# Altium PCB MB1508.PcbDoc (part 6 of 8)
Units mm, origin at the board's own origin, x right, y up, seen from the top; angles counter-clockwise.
Board outline 129 x 77 mm, 4 copper layers (Top Layer, GND, POWER, Bottom Layer), stack 1.582 mm thick; 399 components, 297 nets, 1407 pads, 1316 vias.
Unrouted connection lines stored in the file: 535.
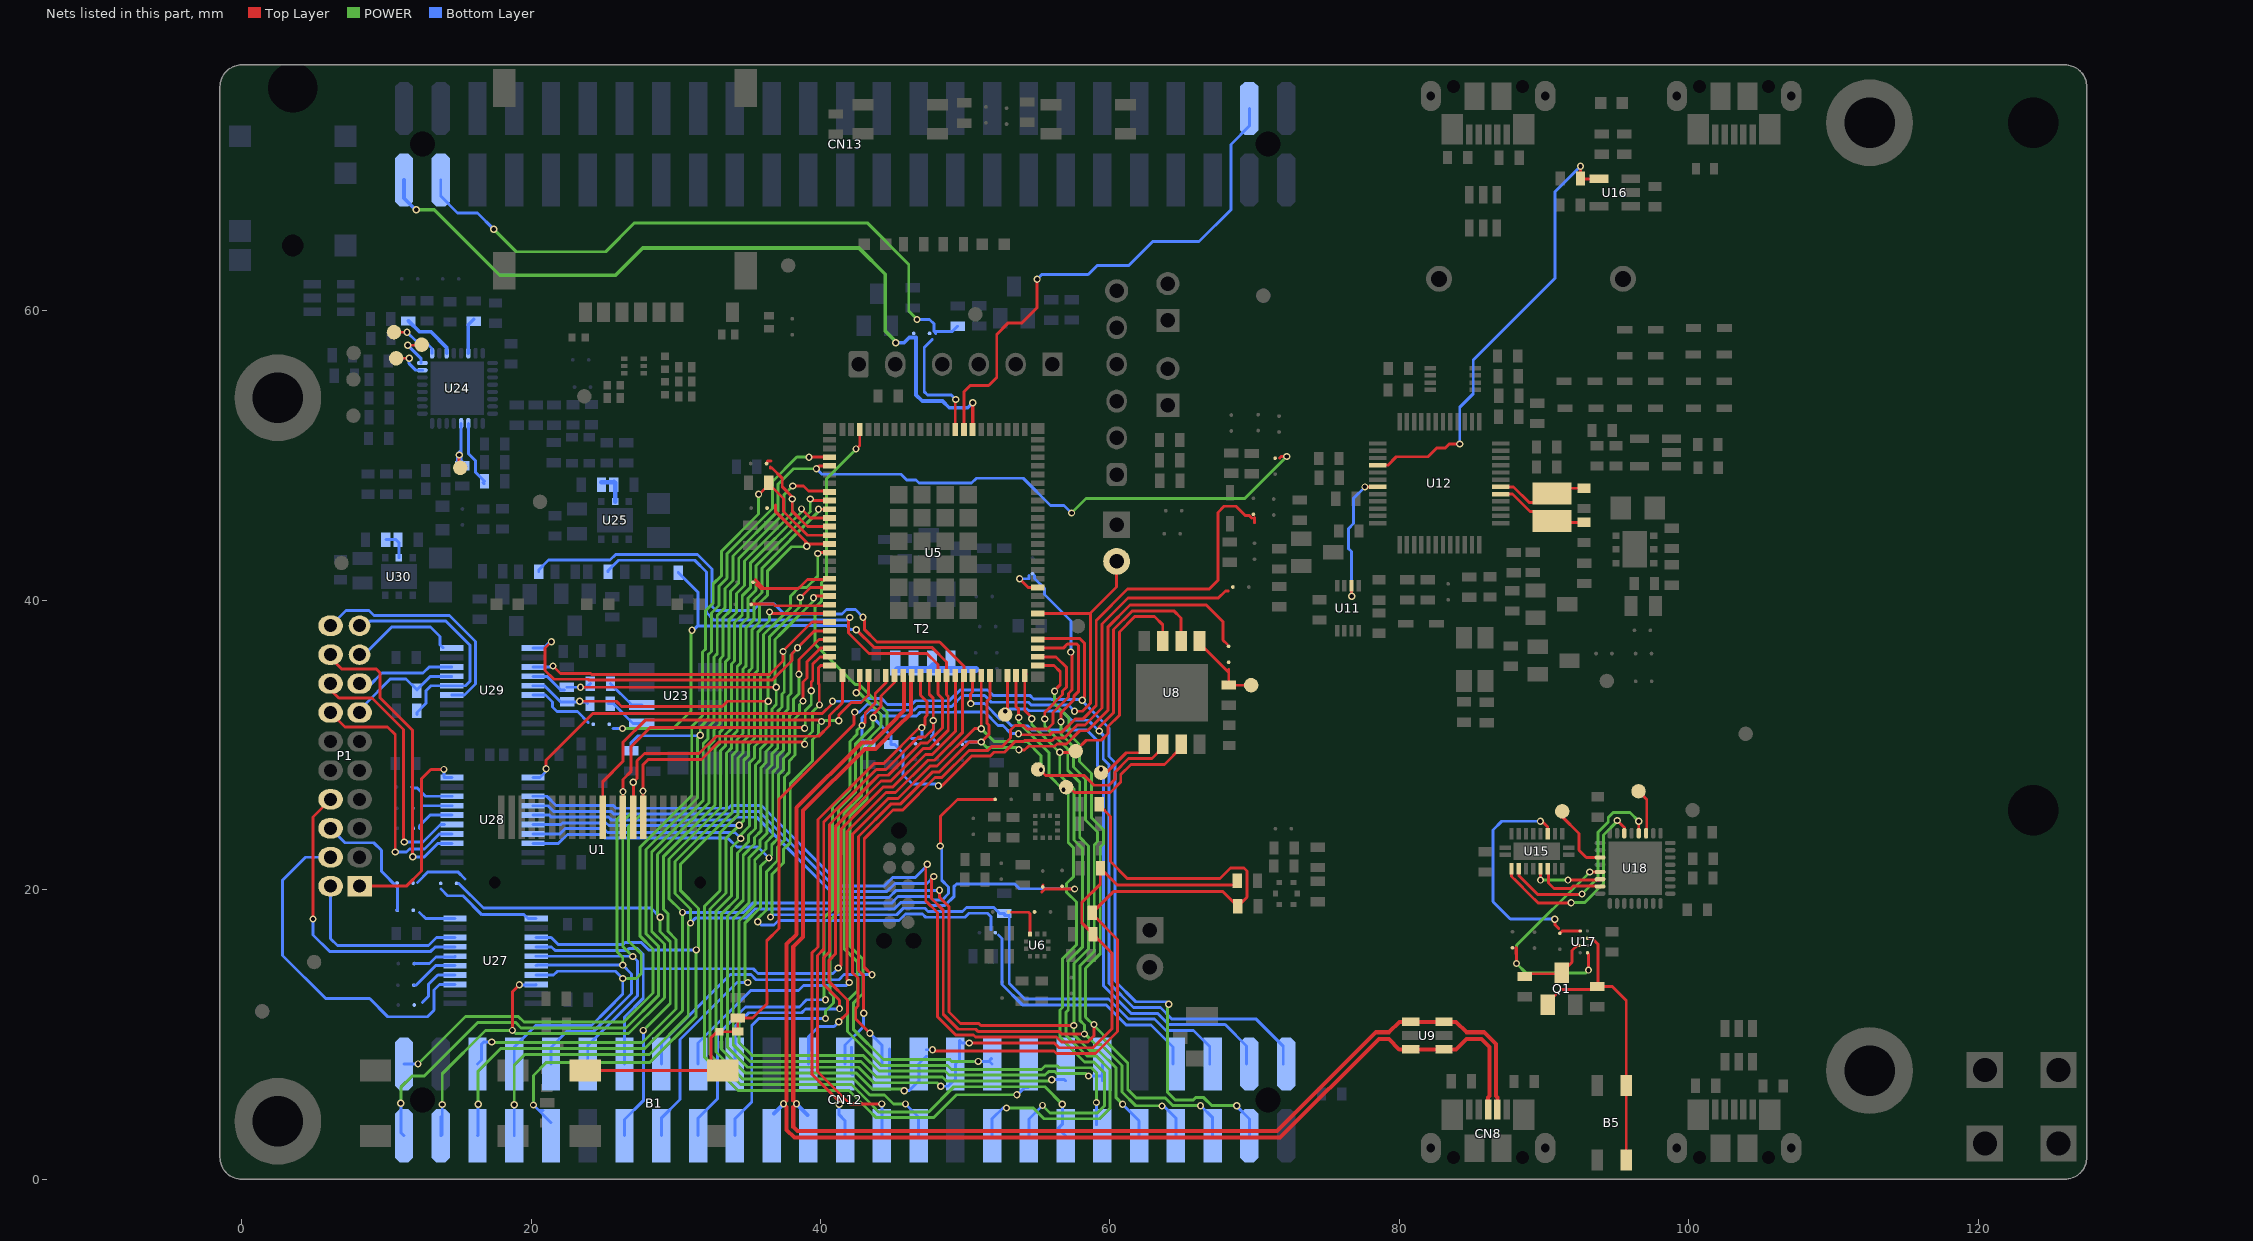
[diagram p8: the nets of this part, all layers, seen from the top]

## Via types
v1: diameter 0.5, hole 0.3, Top Layer to Bottom Layer, tented both sides, 1301 vias
v2: diameter 0.65, hole 0.4, Top Layer to Bottom Layer, tented both sides, 14 vias
v3: diameter 0.5/0.5/0.5/0.5 (per signal layer), hole 0.3, Top Layer to Bottom Layer, tented both sides, 1 vias

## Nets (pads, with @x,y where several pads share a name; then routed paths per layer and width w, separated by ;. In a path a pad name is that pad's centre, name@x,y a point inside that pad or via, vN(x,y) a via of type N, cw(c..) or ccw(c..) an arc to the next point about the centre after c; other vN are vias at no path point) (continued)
NetR93_2: R93.2 U24.3 | length 4.6
  Bottom Layer w0.2: U24.3@15.663,52.225 15.663,50.141 16.16,49.644 16.16,48.851 R93.2@16.78,48.231 ; R93.2@16.678,48.13 R93.2@16.755,48.054
NetR95_2: R95.2 R104.1 U25.5 | length 2.3
  Bottom Layer w0.3: R104.1@24.843,48.155 25.679,48.155 25.731,48.208 25.809,48.129 U25.5@25.809,46.823
NetR97_2: R97.2 TP10.1 U24.4 | length 5.8
  Top Layer w0.2: v1(15.031,50.047) 15.031,49.232 TP10.1@15.106,49.158
  Bottom Layer w0.2: R97.2@14.913,49.471 14.913,50.127 15.163,50.377 ; v1@15.057,50.047 R97.2@15.057,49.455 ; R97.2@15.163,49.612 15.163,50.377 ; U24.4@15.163,52.225 15.163,50.377 ; R97.2@15.213,49.099 15.213,49.299 R97.2@15.057,49.455 ; R97.2@15.213,49.612 R97.2@15.057,49.455
NetR99_1: R99.1 U23.6 | length 2.8
  Bottom Layer w0.2: R99.1@25.493,34.239 26.966,32.766 U23.6@27.654,32.766
NetR100_1: R100.1 U23.5 | length 2.9
  Bottom Layer w0.2: R100.1@25.306,32.867 25.68,32.867 27.051,31.496 U23.5@27.654,31.496
NetR102_1: R102.1 U24.22 | length 2.5
  Bottom Layer w0.254: U24.22@15.663,57.075 15.663,59.05 R102.1@16.032,59.419
NetR110_1: R110.1 U24.19 | length 3.8
  Bottom Layer w0.254: R110.1@11.527,59.31 12.285,58.552 13.086,58.552 14.163,57.475 U24.19@14.163,57.075
NetR117_2: R117.2 R119.1 U30.5 | length 2
  Bottom Layer w0.2: R119.1@9.965,44.199 10.65,44.199 10.866,43.983 U30.5@10.866,42.943
NetSB1_2: SB1.2 U5.68 | length 6.3
  Top Layer w0.2: 35.496,41.43 36.099,40.826 ; 35.566,41.114 35.854,40.827 38.487,40.827 39.107,41.447 40.567,41.447 U5.68@40.613,41.494
NetSB4_1: SB4.1 U5.71 | length 5.5
  Top Layer w0.2: SB4.1@35.207,39.716 35.23,39.739 36.742,39.739 36.854,39.626 40.546,39.626 U5.71@40.613,39.694
NetSB9_1: SB9.1 SB13.1 U6.5 | length 2.7
  Top Layer w0.2: 53.198,18.444 54.374,18.444 54.48,18.338 U6.5@54.48,16.939
NetSB30_1: SB30.1 U17.D2 U18.5 | length 17.2
  Top Layer w0.2: 88.072,15.565 88.072,16 88.097,15.975 v1(88.097,14.905) ; U17.D2@92.999,15.65 93.075,15.573 v1(93.075,14.448) ; v1(93.165,21.229) U18.5@93.872,21.229
  POWER w0.2: v1(93.075,14.448) 92.862,14.234 88.768,14.234 v1(88.097,14.905) 88.097,16.16 v1(93.165,21.229)
NetSB32_1: SB32.1 U15.14 U17.A1 | length 16.6
  Top Layer w0.2: v1(89.746,24.731) 89.858,24.731 90.256,24.332 U15.14@90.256,23.858 ; v1(90.745,17.966) 90.745,17.591 91.018,17.318 ; SB32.1@91.094,16.988 91.256,17.15 U17.A1@92.499,17.15
  Bottom Layer w0.2: v1(89.746,24.731) 87.077,24.731 86.465,24.119 86.465,19.176 87.671,17.97 90.741,17.97 v1(90.745,17.966)
NetSB42_2: SB42.2 T2.5 T2.6 T2.7 T2.8 | length 5.8
  Bottom Layer w0.5: T2.8@45.315,35.216 T2.6@47.553,35.216 ; T2.6@47.825,35.488 T2.6@47.553,35.216 ; SB42.2@50.722,35.216 T2.6@47.553,35.216
NetSB49_2: SB49.2 U29.6 | length 4.8
  Bottom Layer w0.2: U29.6@20.121,33.448 21.002,33.448 21.473,32.977 21.473,32.629 21.794,32.309 23.209,32.309 23.954,31.563
NetSB53_2: SB53.2 U27.1 | length 7.4
  Bottom Layer w0.2: 13.769,20.046 14.231,19.584 15.291,19.584 16.597,18.278 19.511,18.278 19.786,18.004 U27.1@20.353,18.004
NetSB57_1: SB57.1 U27.20 | length 2.6
  Bottom Layer w0.2: 12.292,18.431 12.719,18.004 U27.20@14.753,18.004
NetTP3_1: TP3.1 U24.17 | length 3.4
  Top Layer w0.2: TP3.1@10.526,58.527 v1(11.426,58.527)
  Bottom Layer w0.2: v1(11.426,58.527) 12.039,57.914 12.653,57.914 13.163,57.403 U24.17@13.163,57.075
NetTP4_1: TP4.1 U24.16 | length 2.6
  Top Layer w0.2: v1(11.477,57.627) 12.398,57.627 TP4.1@12.436,57.665
  Bottom Layer w0.2: v1(11.477,57.627) 12.405,56.698 U24.16@12.405,56.4
NetTP5_1: TP5.1 U24.15 | length 2.4
  Top Layer w0.2: TP5.1@10.677,56.727 v1(11.577,56.727)
  Bottom Layer w0.2: v1(11.577,56.727) 11.577,56.352 12.029,55.9 U24.15@12.488,55.9
NetTP21_1: TP21.1 U18.3 | length 4.8
  Top Layer w0.2: TP21.1@91.256,25.416 91.256,25.043 92.415,23.884 92.415,22.734 92.92,22.229 U18.3@93.872,22.229
NetTP23_1: TP23.1 U18.27 | length 3.2
  Top Layer w0.2: TP23.1@96.528,26.807 97.097,26.238 97.097,23.954 U18.27@97.047,23.904
NetU11_2: U11.2 U12.31 | length 9.8
  Top Layer w0.2: v1@76.699,40.507 U11.2@76.699,41.001 U11.2@76.699,41.255 ; v1(77.622,47.838) U12.31@78.519,47.838
  Bottom Layer w0.2: v1(76.714,40.273) 76.699,40.289 76.699,43.367 76.475,43.59 76.475,44.933 76.842,45.3 76.842,47.058 v1(77.622,47.838)
NetU15_2: U15.2 U18.30 | length 14
  Top Layer w0.2: U15.2@87.756,21.458 87.756,20.918 88.09,20.584 89.036,19.638 89.578,19.096 v1(91.869,19.096) ; v1(95.057,24.786) 95.547,24.295 U18.30@95.547,23.904
  POWER w0.2: v1(91.869,19.096) 91.895,19.122 92.813,19.122 94.115,20.425 94.115,21.622 ; 94.115,21.623 94.115,23.791 95.057,24.733 v1(95.057,24.786)
NetU15_3: U15.3 U18.28 | length 14.8
  Top Layer w0.2: U15.3@88.256,21.458 88.252,21.455 U15.3@88.254,21.453 ; U15.3@88.306,21.401 U15.3@88.254,21.453 ; v1(92.618,19.706) 92.596,19.684 89.556,19.684 88.482,20.758 88.254,20.986 U15.3@88.254,21.453 ; U18.28@96.547,23.904 v1(96.547,24.739)
  POWER w0.2: v1(92.618,19.706) 93.715,20.803 93.715,21.457 ; 93.715,21.457 93.715,23.957 94.435,24.677 94.435,24.986 94.785,25.336 95.95,25.336 v1(96.547,24.739)
NetU15_6: U15.6 U18.6 | length 4.9
  Top Layer w0.2: v1@89.756,20.704 U15.6@89.756,21.458 ; v1(91.651,20.667) 91.663,20.679 93.822,20.679 U18.6@93.872,20.729
  POWER w0.2: v1(89.756,20.667) v1(91.651,20.667)
NetU15_7: U15.7 U18.7 | length 4.8
  Top Layer w0.2: U15.7@90.256,21.458 90.306,21.408 90.306,20.472 90.694,20.084 91.846,20.084 92.018,20.256 93.599,20.256 93.66,20.195 93.838,20.195 U18.7@93.872,20.229
NRST: B1.1 B1.2 C6.2 JP2.2 R12.2 U4.1 U5.7 | length 71.4
  Top Layer w0.2: B1.1@23.75,7.5 B1.2@33.25,7.5 ; B1.2@32.429,7.868 32.429,9.771 32.848,10.19 C6.2@33.021,10.19 34.249,10.19 U4.1@34.278,10.22 R12.2@34.278,11.129 35.3,11.129 36.295,12.124 36.295,12.923 ; 36.288,12.923 36.288,16.476 37.126,17.313 37.126,26.252 42.314,31.44 42.314,32.222 v1(42.368,32.276) ; U5.7@55.013,39.094 58.629,39.094 58.655,39.119 ; v1(57.55,32.337) 58.104,32.337 58.655,32.888 58.655,39.119 ; JP2.2@60.464,42.689 60.464,40.929 58.655,39.119
  Bottom Layer w0.2: v1(42.368,32.276) 42.692,32.276 43.246,32.829 44.033,32.829 44.459,32.403 46.471,32.403 46.731,32.663 49.069,32.663 49.819,33.414 51.346,33.414 51.801,32.959 54.372,32.959 54.558,32.773 55.773,32.773 55.785,32.76 57.128,32.76 v1(57.55,32.337)
OSC_IN: C36.2 U12.5 X1.1 | length 6.6
  Top Layer w0.2: U12.5@87.019,47.338 87.83,47.338 89.029,46.138 89.588,46.138 90.244,45.482 X1.1@90.555,45.482 90.646,45.391 C36.2@92.763,45.391
OSC_OUT: C37.2 U12.6 X1.2 | length 6.6
  Top Layer w0.2: U12.6@87.019,47.838 87.895,47.838 88.985,46.748 89.921,46.748 90.915,47.742 C37.2@92.768,47.742
PA0: CN12.3 U5.4 U28.1 | length 87.6
  Top Layer w0.2: v1(21.04,28.368) 21.04,28.947 24.262,32.169 38.545,32.169 38.55,32.174 40.127,32.174 v1@40.83,32.877 ; U5.4@55.013,37.294 55.092,37.373 57.901,37.373 58.242,37.032 58.242,33.337 58.011,33.105 58.017,33.098 v1(58.087,33.098)
  POWER w0.2: v1(64.064,12.093) 63.988,12.018 63.988,6.001 64.509,5.48 65.758,5.48 65.908,5.63 66.49,5.63 67.04,5.08 v1(68.762,5.08)
  Bottom Layer w0.2: U28.1@20.131,27.757 20.618,27.757 21.04,28.179 v1(21.04,28.368) ; v1(40.83,33.023) 42.874,33.023 43.08,33.229 44.198,33.229 44.625,32.803 46.305,32.803 46.565,33.063 48.903,33.063 49.654,33.814 51.542,33.814 51.921,33.434 54.462,33.434 54.723,33.173 55.938,33.173 55.951,33.16 58.025,33.16 v1(58.087,33.098) 58.084,33.095 58.084,33.041 59.942,31.183 59.942,29.214 59.937,29.208 59.937,29.206 60.35,28.792 60.35,13.698 61.786,12.262 63.896,12.262 v1(64.064,12.093) ; v1(68.762,5.08) 68.762,5.044 69.64,4.166 CN12.3@69.64,3.005
PA0_C: P1.1 U28.20 | length 14
  Top Layer w0.2: P1.1@8.15,20.246 11.38,20.246 12.431,21.297 12.431,27.676 13.072,28.317 v1(13.977,28.317)
  Bottom Layer w0.2: v1(13.977,28.317) 13.977,27.782 14.002,27.757 U28.20@14.531,27.757
PA1: CN12.5 U5.1 U28.3 | length 96
  Top Layer w0.2: v1(47.376,21.757) 47.276,21.656 47.276,19.228 48.081,18.423 48.081,11.226 49.35,9.957 50.565,9.957 50.706,9.816 56.313,9.816 56.649,9.479 58.465,9.479 58.896,9.911 v1(58.896,10.69) ; U5.1@55.013,35.494 56.14,35.494 56.565,35.069 56.565,34.17 56.106,33.71 v1(56.179,33.71)
  POWER w0.2: v1(56.179,33.71) 56.179,32.856 57.156,31.879 57.156,31.834 57.161,31.829 57.161,30.776 57.893,30.044 57.893,28.852 58.719,28.025 58.719,24.977 59.55,24.146 59.55,23.169 59.329,22.948 59.329,15.578 58.32,14.569 58.32,11.194 v1@58.896,10.619 ; v1(58.896,10.69) v1@58.896,10.619 ; v1(66.262,5.08) 64.344,5.08 63.823,5.601 61.823,5.601 61.233,6.191 61.233,8.019 59.55,9.702 59.55,9.964 v1@58.896,10.619
  Bottom Layer w0.2: U28.3@20.131,26.457 21.086,26.457 21.725,25.819 25.685,25.819 25.874,25.63 33.641,25.63 33.822,25.811 35.922,25.811 41.461,20.272 44.413,20.272 44.994,20.853 46.551,20.853 47.376,21.679 v1(47.376,21.757) ; v1(66.262,5.08) 67.1,4.242 CN12.5@67.1,3.005
PA1_C: SB61.1 U28.18 | length 3
  Bottom Layer w0.2: SB61.1@11.797,27.102 11.873,27.025 12.135,27.025 12.703,26.457 U28.18@14.531,26.457
PA2: CN12.7 U5.3 U28.4 | length 94
  Top Layer w0.2: v1(47.826,20.912) 47.676,20.762 47.676,19.394 48.481,18.588 48.481,11.392 49.516,10.357 50.73,10.357 50.871,10.216 56.479,10.216 56.665,10.029 v1(58.235,10.029) ; U5.3@55.013,36.694 56.778,36.694 57.058,36.973 57.705,36.973 57.842,36.836 57.842,33.715 57.529,33.401 57.529,33.151 56.611,32.232 v1(56.611,31.602)
  POWER w0.2: v1(56.611,31.602) 56.611,30.75 56.918,30.443 56.928,30.443 57.484,29.887 57.484,28.473 58.319,27.639 58.319,24.811 59.15,23.98 59.15,23.335 58.918,23.102 58.918,15.732 57.92,14.735 57.92,10.976 58.235,10.661 v1(58.235,10.029) 58.244,10.029 58.265,10.05 59.013,9.302 59.385,9.302 60.833,7.854 60.833,6.026 61.781,5.077 63.569,5.077 v1(63.595,5.051)
  Bottom Layer w0.2: U28.4@20.131,25.807 21.171,25.807 21.559,25.419 25.519,25.419 25.708,25.23 33.807,25.23 33.988,25.411 35.756,25.411 41.295,19.872 44.579,19.872 45.144,20.437 47.35,20.437 v1(47.826,20.912) ; v1(63.595,5.051) 63.719,5.051 64.56,4.21 CN12.7@64.56,3.005
PA2_C: SB60.1 U28.17 | length 2
  Bottom Layer w0.2: 12.509,25.807 U28.17@14.531,25.807
PA3: CN12.9 U5.2 U28.5 | length 88
  Top Layer w0.2: v1@48.076,19.962 v1@48.226,19.812 ; v1(48.226,19.96) v1@48.226,19.812 ; U5.2@55.013,36.094 56.273,36.094 56.991,35.376 56.991,33.994 56.729,33.733 56.729,33.482 55.495,32.248 v1(55.495,31.804) ; v1@55.514,31.7 v1@55.514,31.804 ; v1(57.503,10.616) 51.079,10.616 50.938,10.757 49.681,10.757 48.881,11.557 48.881,18.826 48.226,19.482 v1@48.226,19.812
  POWER w0.2: v1(55.495,31.804) 55.495,31.3 56.752,30.043 56.762,30.043 57.084,29.721 57.084,28.258 57.919,27.423 57.919,23.626 58.518,23.027 58.518,15.898 57.52,14.9 57.52,10.634 v1(57.503,10.616) ; v1@57.52,10.598 v1(57.503,10.616) ; v1(60.877,5.175) 60.433,5.62 60.433,7.688 59.219,8.902 58.585,8.902 57.503,9.984 v1(57.503,10.616)
  Bottom Layer w0.2: U28.5@20.131,25.157 21.255,25.157 21.393,25.019 25.354,25.019 25.542,24.83 33.972,24.83 34.153,25.011 35.59,25.011 41.13,19.472 44.744,19.472 45.235,19.962 45.237,19.96 v1(48.226,19.96) ; v1(60.877,5.175) 62.02,4.032 CN12.9@62.02,3.005
PA3_C: SB58.1 U28.16 | length 2.7
  Bottom Layer w0.2: 12.296,24.246 12.296,24.418 13.035,25.157 U28.16@14.531,25.157
PA4: CN12.11 U5.82 | length 49.4
  Top Layer w0.2: v1(42.464,33.614) 42.713,33.862 U5.82@42.713,34.794
  POWER w0.2: v1(42.464,33.614) 42.682,33.614 44.189,32.107 44.189,31.28 42.831,29.922 42.831,26.48 41.633,25.282 41.633,22.424 41.641,22.416 41.641,15.92 42.542,15.019 42.542,12.998 41.869,12.325 41.869,10.194 44.198,7.865 48.768,7.865 49.045,7.588 55.271,7.588 55.51,7.827 56.368,7.827 56.494,7.702 58.722,7.702 59.065,7.359 v1(59.065,5.293)
  Bottom Layer w0.2: CN12.11@59.065,3.758 v1(59.065,5.293)
PA5: CN12.13 U5.72 U28.6 | length 80.5
  Top Layer w0.2: v1(36.48,39.189) 36.48,39.172 36.559,39.094 U5.72@40.613,39.094
  POWER w0.2: v1(36.48,39.189) 36.48,38.615 35.665,37.799 35.665,35.149 35.445,34.928 35.445,30.465 35.038,30.058 35.038,29.281 34.7,28.943 34.7,24.78 v1(34.381,24.461) 33.459,23.539 33.459,20.973 33.462,20.97 33.462,19.769 32.372,18.679 32.372,8.625 34.464,6.532 42.137,6.532 43.69,4.979 43.69,4.973 44.012,4.651 47.475,4.651 49.21,6.386 55.507,6.386 v1(56.711,5.182)
  Bottom Layer w0.2: U28.6@20.131,24.507 22.066,24.507 22.178,24.619 25.188,24.619 25.377,24.43 v1@34.381,24.43 ; v1(56.711,5.182) 56.711,3.792 56.432,3.513 CN12.13@56.94,3.005
PA5_C: P1.18 U28.15 | length 17.7
  Top Layer w0.2: P1.18@6.15,34.246 6.15,33.81 6.714,33.246 9.015,33.246 11.189,31.072 11.189,23.374 11.232,23.331 v1(11.232,23.296)
  Bottom Layer w0.2: v1(11.232,23.296) 12.53,23.296 13.742,24.507 U28.15@14.015,24.507
PA6: CN12.15 TP16.1 U5.100 U8.7 | length 51.3
  Top Layer w0.2: U5.100@53.513,34.794 53.513,32.651 53.695,32.469 v1(53.695,31.906) ; TP16.1@56.769,27.055 57.145,27.055 57.18,27.09 57.545,26.725 60.032,26.725 60.75,27.443 60.75,27.96 61.454,28.664 63.775,28.664 64.921,29.809 U8.7@64.921,30.039
  POWER w0.2: v1(53.695,31.906) 53.695,31.553 55.784,29.464 55.784,27.907 v1(56.788,26.903) 57.119,26.572 57.119,23.272 57.47,22.921 57.47,20.89 57.009,20.428 57.009,19.828 57.689,19.147 57.689,16.2 56.72,15.232 56.72,11.857 56.553,11.689 56.553,9.803 58.254,8.102 58.888,8.102 59.615,7.375 59.615,5.065 59.124,4.574 55.865,4.574 v1(55.34,5.099)
  Bottom Layer w0.2: CN12.15@54.4,3.005 54.4,4.159 v1(55.34,5.099)
PA7: CN12.17 TP18.1 U5.101 U8.3 | length 60
  Top Layer w0.2: U5.101@54.113,34.794 54.113,32.378 54.595,31.896 v1(54.595,31.823) ; U5.101@54.113,34.996 U5.101@54.214,34.895 ; v1(56.534,29.493) 57.551,29.493 TP18.1@57.637,29.579 ; TP18.1@57.637,29.725 57.754,29.725 58.359,30.33 59.398,30.33 59.87,30.802 59.87,31.275 60.655,32.06 60.655,37.813 61.718,38.876 63.083,38.876 63.651,38.308 U8.3@63.651,37.189
  POWER w0.2: v1(52.851,4.921) 54.705,4.921 55.452,4.174 59.289,4.174 60.015,4.899 60.015,7.54 59.053,8.502 58.42,8.502 56.953,9.969 56.953,11.523 57.12,11.691 57.12,15.066 58.118,16.064 58.118,22.839 57.519,23.438 57.519,26.95 56.534,27.934 v1(56.534,29.493) 56.524,29.493 54.595,31.422 v1(54.595,31.823)
  Bottom Layer w0.2: CN12.17@51.86,3.005 51.86,4.18 52.601,4.921 v1(52.851,4.921)
PA8: CN12.21 U5.65 U28.7 | length 70.4
  Top Layer w0.2: v1(39.807,43.24) 39.861,43.294 U5.65@40.613,43.294
  POWER w0.2: v1(39.807,43.24) 39.807,41.67 39.028,40.891 38.525,40.891 37.939,40.306 37.939,39.508 36.985,38.554 36.065,37.634 36.065,34.983 35.845,34.763 35.845,30.299 35.438,29.893 35.438,29.116 35.1,28.778 35.1,24.402 34.483,23.785 v1(34.483,23.547) 33.859,22.923 33.859,21.139 33.862,21.136 33.862,19.603 32.772,18.513 32.772,8.79 34.63,6.932 42.303,6.932 43.409,5.826 44.428,5.826 45.053,5.201 v1(45.872,5.201)
  Bottom Layer w0.2: U28.7@20.131,23.857 21.982,23.857 22.344,24.219 25.022,24.219 25.279,23.962 34.102,23.962 34.483,23.582 v1(34.483,23.547) ; v1(45.872,5.201) 46.78,4.293 CN12.21@46.78,3.005
PA8_C: P1.17 U28.14 | length 17.6
  Top Layer w0.2: P1.17@6.15,32.246 7.15,31.246 10.087,31.246 10.611,30.721 v1(10.611,22.606)
  Bottom Layer w0.2: v1(10.611,22.606) 11.383,22.606 11.602,22.826 12.626,22.826 13.657,23.857 U28.14@14.531,23.857
PA9: CN12.23 SB44.2 U5.90 | length 40.7
  Top Layer w0.2: v1(44.24,5.201) 42.033,5.201 39.8,7.433 39.8,15.462 40.223,15.885 40.223,24.679 43.857,28.313 44.522,28.313 46.757,30.548 47.225,30.548 47.789,31.112 v1(47.789,31.694) 47.789,33.239 47.513,33.515 U5.90@47.513,34.794
  Bottom Layer w0.2: CN12.23@44.24,3.005 v1(44.24,5.201) v1@44.24,5.227 ; v1(47.789,31.694) 47.789,30.738 47.682,30.631 47.733,30.58 47.682,30.53 47.945,30.267
PA10: CN12.25 SB46.2 U5.89 | length 38.1
  Top Layer w0.2: v1(41.291,5.164) 41.291,5.376 39.4,7.267 39.4,15.628 39.823,16.051 39.823,24.845 43.691,28.713 44.356,28.713 46.849,31.206 v1(47.004,31.206) 47.233,31.435 47.233,31.916 47.349,32.032 47.349,33.011 46.913,33.447 U5.89@46.913,34.794
  Bottom Layer w0.2: v1(41.291,5.164) 41.291,4.445 41.7,4.037 CN12.25@41.7,3.005 ; 46.285,30.44 46.916,30.44 47.004,30.528 v1(47.004,31.206)
PA11: CN8.2 CN12.27 U5.88 U9.1 U9.6 | length 93.3
  Top Layer w0.279: U5.88@46.313,34.794 46.242,34.722 46.242,32.187 45.264,31.209 45.264,31.206 43.788,29.73 43.058,29.73 38.806,25.477 38.806,25.442 38.792,25.428 38.792,16.735 38.119,16.061 38.119,5.426 v1(38.34,5.205) 38.119,4.984 38.119,3.6 38.398,3.321 71.558,3.321 78.391,10.154 79.292,10.154 80.014,10.875 U9.1@80.784,10.875 U9.6@83.084,10.875 83.921,10.875 84.642,10.154 85.858,10.154 86.684,9.328 86.684,5.736 86.78,5.64 CN8.2@86.78,4.81
  Bottom Layer w0.279: v1(38.34,5.205) CN12.27@39.103,4.442
PA12: CN8.3 CN12.29 U5.87 U9.3 U9.4 | length 93.1
  Top Layer w0.279: U5.87@45.713,34.794 45.784,34.722 45.784,32.376 44.807,31.398 44.807,31.395 43.598,30.187 42.869,30.187 38.348,25.667 38.348,25.631 38.334,25.617 38.334,16.924 37.661,16.251 37.661,5.426 v1(37.44,5.205) 37.661,4.984 37.661,3.411 38.209,2.864 71.748,2.864 78.58,9.696 79.272,9.696 79.993,8.975 U9.3@80.784,8.975 U9.4@83.084,8.975 83.92,8.975 84.642,9.696 85.668,9.696 86.226,9.138 86.226,5.736 86.13,5.64 CN8.3@86.13,4.81
  Bottom Layer w0.279: CN12.29@36.783,4.548 v1(37.44,5.205)
PA13: CN12.31 R81.1 SB17.1 U5.86 | length 75.8
  Top Layer w0.2: v1(43.639,31.879) 43.639,32.118 44.184,32.663 44.184,33.39 45.113,34.319 U5.86@45.113,34.794 ; v1@48.344,27.142 50.432,29.23 51.721,29.23 51.995,29.504 52.72,29.504 53.454,30.238 53.458,30.234 54.036,30.234 54.11,30.308 54.136,30.308 54.14,30.313 56.01,30.313 56.18,30.482 56.839,30.482 57.744,31.387 58.285,31.387 59.455,32.557 59.455,38.36 61.245,40.151 67.492,40.151 67.983,40.642 68.176,40.642
  POWER w0.2: v1(40.35,11.101) 40.35,11.618 40.9,12.168 40.9,12.624 40.651,12.873 40.651,17.895 41.241,18.484 41.241,22.251 41.233,22.259 41.233,25.55 42.431,26.748 42.431,30.088 43.639,31.296 v1(43.639,31.879)
  Bottom Layer w0.2: CN12.31@34.08,3.005 34.08,4.154 35.248,5.322 35.248,10.614 35.735,11.101 v1(40.35,11.101) ; v1(43.639,31.879) 44.884,30.634 R81.1@44.884,30.034 45.129,30.034 45.708,29.455 45.708,27.938 46.349,27.298 47.932,27.298 v1@48.088,27.142
  other v1: 48.148,27.179
PA14: CN12.33 R83.1 SB19.1 U5.85 | length 83.8
  Top Layer w0.2: v1(42.864,31.355) 43.089,31.58 43.089,32.211 43.784,32.905 43.784,33.556 44.513,34.285 U5.85@44.513,34.794 ; v1(53.685,30.786) 53.758,30.713 55.844,30.713 56.014,30.882 56.673,30.882 57.578,31.787 58.119,31.787 59.055,32.723 59.055,38.614 61.218,40.777 66.867,40.777 67.472,41.382 67.472,46.079 67.892,46.499 68.721,46.499 69.353,45.866 69.627,45.866 69.801,45.692 ; 69.987,45.362 69.987,45.725 ; 69.987,45.725 69.99,45.728 69.987,45.728 69.987,45.725
  POWER w0.2: v1(40.35,12.396) 40.251,12.495 40.251,18.06 40.841,18.65 40.841,22.085 40.833,22.093 40.833,25.715 42.031,26.914 42.031,30.254 42.51,30.732 42.51,31 v1(42.864,31.355)
  Bottom Layer w0.2: CN12.33@31.54,3.005 31.54,4.21 32.886,5.556 32.886,9.977 34.809,11.901 38.543,11.901 39.038,12.396 v1(40.35,12.396) ; R83.1@43.309,30.059 43.178,30.059 42.864,30.374 v1(42.864,31.355) 42.864,31.882 43.411,32.429 43.867,32.429 44.293,32.003 46.636,32.003 46.897,32.263 49.234,32.263 49.241,32.27 51.358,32.27 52.268,31.36 52.602,31.36 53.177,30.786 v1(53.685,30.786)
PA15: CN12.35 U5.75 U28.8 | length 57.3
  Top Layer w0.2: v1(38.507,34.889) 38.507,35.914 39.887,37.294 U5.75@40.613,37.294
  POWER w0.2: v1(34.965,13.59) 34.772,13.783 34.772,17.685 35.862,18.775 35.862,21.624 v1(36.438,22.2) 36.633,22.395 36.633,23.106 37.1,23.574 37.1,27.949 37.438,28.287 37.438,29.064 37.845,29.471 37.845,32.001 38.145,32.301 38.145,33.162 ; 38.146,33.163 38.146,33.178 38.507,33.54 v1(38.507,34.889)
  Bottom Layer w0.2: U28.8@20.131,23.207 21.898,23.207 22.509,23.819 24.857,23.819 25.113,23.562 33.616,23.562 34.227,22.951 35.687,22.951 v1(36.438,22.2) ; CN12.35@29,3.005 29,4.21 30.295,5.505 30.295,9.657 34.229,13.59 v1(34.965,13.59)
PA15_C: P1.19 U28.13 | length 20.7
  Top Layer w0.2: P1.19@6.15,36.246 6.15,36.008 6.912,35.246 8.564,35.246 9.307,35.246 9.564,34.99 9.564,33.263 11.805,31.021 v1@11.805,22.403
  Bottom Layer w0.2: v1(11.83,22.276) 12.641,22.276 13.573,23.207 U28.13@14.531,23.207
PB0: CN12.2 TP14.1 U5.99 U8.2 | length 56.9
  Top Layer w0.2: v1(52.761,32.334) 52.913,32.486 U5.99@52.913,34.794 ; v1(59.255,30.965) 59.255,31.226 60.255,32.226 60.255,37.978 61.552,39.276 64.414,39.276 64.921,38.768 U8.2@64.921,37.189
  Bottom Layer w0.2: v1(52.761,32.334) 52.914,32.487 54.278,32.487 54.392,32.373 55.607,32.373 55.62,32.36 56.675,32.36 57.323,31.712 57.778,31.712 ; 57.779,31.713 58.506,31.713 v1(59.255,30.965) ; v1(59.255,30.965) 59.542,30.677 59.542,29.379 59.537,29.374 59.537,29.04 59.95,28.627 59.95,13.532 61.621,11.862 63.485,11.862 64.265,11.081 70.078,11.081 71.98,9.179 CN12.2@71.98,7.955
PB1: CN12.4 TP19.1 U5.95 U8.5 | length 45.9
  Top Layer w0.2: v1(50.375,32.864) 50.375,33.526 50.513,33.664 U5.95@50.513,34.794 ; TP19.1@59.386,28.09 59.749,28.09 61.122,29.464 62.26,29.464 62.381,29.585 U8.5@62.381,30.039
  Bottom Layer w0.2: v1(50.375,32.864) 51.33,32.864 52.41,31.784 52.744,31.784 53.193,31.336 54.304,31.336 54.588,31.052 58.389,31.052 59.142,30.299 59.142,29.545 59.137,29.54 59.137,28.568 v1(59.379,28.325) 59.55,28.154 59.55,13.366 61.455,11.462 63.282,11.462 64.062,10.681 67.963,10.681 69.44,9.205 CN12.4@69.44,7.955
PB2_R: CN12.6 R72.1 U1.11 U5.83 | length 79.6
  Top Layer w0.2: U1.11@24.95,24.999 24.95,27.469 26.359,28.878 26.359,30.191 27.885,31.717 39.978,31.717 v1(40.071,31.624) ; v1(41.264,31.686) 41.264,32.085 42.126,32.947 42.798,32.947 43.313,33.462 U5.83@43.313,34.794
  POWER w0.2: v1(36.55,18.113) 36.662,18.224 36.662,21.08 37.433,21.851 37.433,22.775 37.912,23.254 37.912,27.35 39.452,28.891 39.452,30.373 ; 39.454,30.375 39.852,30.773 39.852,31.405 v1(40.071,31.624) 40.133,31.686 v1(41.264,31.686) 41.403,31.686 v1@41.341,31.624
  Bottom Layer w0.2: v1(36.55,18.113) 36.709,18.272 45.265,18.272 45.713,18.719 47.219,18.719 47.436,18.502 49.818,18.502 50.095,18.779 51.971,18.779 52.386,18.364 R72.1@52.709,18.364 ; R72.1@52.709,18.23 53.046,18.23 53.046,13.516 54.114,12.448 59.902,12.448 61.289,11.062 63.085,11.062 63.865,10.281 65.776,10.281 66.9,9.157 CN12.6@66.9,7.955
PB3: CN12.8 SB40.2 U5.76 | length 57.4
  Top Layer w0.2: v1(38.788,33.042) 38.788,34.356 39.063,34.631 39.063,35.757 40,36.694 U5.76@40.613,36.694 U5.76@40.605,36.701
  POWER w0.2: v1(35.665,17.783) 35.665,18.013 36.262,18.609 36.262,21.246 37.033,22.017 37.033,22.941 37.5,23.408 37.5,24.004 ; 37.512,24.004 37.512,27.795 37.838,28.122 37.838,28.898 38.245,29.305 38.245,31.835 38.545,32.135 38.545,32.8 v1(38.788,33.042)
  Bottom Layer w0.2: v1(35.665,17.783) 35.885,17.563 36.791,17.563 37.1,17.872 45.431,17.872 45.878,18.319 47.053,18.319 47.271,18.102 49.987,18.102 50.263,18.379 51.535,18.379 51.775,18.139 51.775,17.237 51.777,17.236 ; 52.305,16.88 52.553,16.632 52.553,13.444 53.948,12.048 59.737,12.048 61.124,10.662 62.838,10.662 64.36,9.14 CN12.8@64.36,7.955
PB4: CN12.12 U5.74 U29.1 | length 81.6
  Top Layer w0.2: v1(21.406,37.144) 20.966,36.704 20.966,35.161 21.58,34.546 23.954,34.546 24.018,34.482 36.652,34.482 38.021,35.851 38.021,36.328 v1(38.41,36.717) 39.587,37.894 U5.74@40.613,37.894
  POWER w0.2: 37.745,33.327 37.745,32.467 37.445,32.167 37.445,29.637 37.038,29.23 37.038,28.453 36.7,28.115 36.7,23.739 36.233,23.272 36.233,22.822 35.459,22.048 35.459,21.801 35.462,21.799 35.462,18.94 34.372,17.851 34.372,9.453 35.293,8.532 42.965,8.532 44.033,7.465 48.602,7.465 48.879,7.188 55.508,7.188 55.747,7.427 56.203,7.427 56.328,7.302 58.344,7.302 v1(58.515,7.131) ; 37.746,33.328 37.746,33.352 37.957,33.564 37.957,36.228 38.41,36.681 v1(38.41,36.717)
  Bottom Layer w0.2: U29.1@20.121,36.698 20.881,36.698 21.328,37.144 v1(21.406,37.144) ; v1(58.515,7.131) CN12.12@59.48,7.131 ; CN12.12@59.48,6.801 CN12.12@59.48,7.131 ; CN12.12@59.48,7.955 CN12.12@59.48,7.131
PB4_C: P1.9 U29.20 | length 7.5
  Bottom Layer w0.2: P1.9@8.15,36.246 8.459,36.246 10.373,38.16 13.059,38.16 13.709,37.51 13.709,36.926 U29.20@13.909,36.726
PB5: CN12.14 U5.73 U29.3 | length 75.4
  Top Layer w0.2: v1(21.516,35.464) 22.034,34.946 24.12,34.946 24.184,34.882 36.486,34.882 37.415,35.811 v1(37.415,36.463) 37.415,36.5 39.409,38.494 U5.73@40.613,38.494
  POWER w0.2: 37.345,33.493 37.345,32.632 37.045,32.332 37.045,29.802 36.638,29.396 36.638,28.619 36.3,28.281 36.3,23.905 35.833,23.438 35.833,22.987 35.059,22.214 35.059,21.636 35.062,21.633 35.062,19.106 33.972,18.016 33.972,9.287 35.127,8.132 42.8,8.132 43.867,7.065 48.437,7.065 48.713,6.788 55.886,6.788 v1(55.975,6.877) ; 37.346,33.494 37.346,33.518 37.494,33.666 37.494,36.385 v1(37.415,36.463)
  Bottom Layer w0.2: U29.3@20.121,35.398 21.45,35.398 v1(21.516,35.464) ; v1(55.975,6.877) 56.864,6.877 CN12.14@56.94,6.801
PB5_C: P1.8 U29.18 | length 7
  Bottom Layer w0.2: P1.8@8.15,34.246 8.298,34.098 8.812,34.098 9.69,34.976 12.541,34.976 12.964,35.398 U29.18@14.521,35.398
PB6: CN12.16 SB3.1 U5.64 | length 69.5
  Top Layer w0.2: 36.877,46.583 36.877,46.154 v1@39.113,43.919 ; v1@38.96,43.777 38.96,44.048 ; v1@39.113,43.702 39.304,43.894 ; v1@39.113,43.894 39.304,43.894 ; U5.64@40.613,43.894 39.304,43.894
  POWER w0.2: v1@39.113,43.702 38.002,43.702 36.349,42.05 36.349,40.371 35.792,39.813 35.792,38.492 35.265,37.965 35.265,35.314 35.045,35.094 35.045,30.631 34.638,30.224 34.638,29.447 34.3,29.109 34.3,25.182 33.059,23.941 33.059,20.807 33.062,20.805 33.062,19.935 31.972,18.845 31.972,8.459 34.298,6.132 41.971,6.132 42.942,5.162 42.942,5.156 43.29,4.808 ; 43.29,4.807 43.847,4.251 47.811,4.251 49.396,5.836 v1(53.573,5.836)
  Bottom Layer w0.2: v1(53.573,5.836) 53.613,5.836 54.121,6.344 CN12.16@54.374,6.344
  other v1: 39.057,43.74
PB7_R: CN12.18 U5.48 | length 57.8
  Top Layer w0.2: v1@42.45,50.437 42.713,50.7 U5.48@42.713,51.794
  POWER w0.2: 40.401,46.059 40.401,41.567 40.061,41.227 40.061,40.409 40.066,40.404 40.066,39.937 39.623,39.494 39.623,36.964 42.398,34.189 42.673,34.189 44.589,32.273 44.589,31.115 43.231,29.757 43.231,26.315 42.033,25.116 42.033,22.59 42.041,22.582 42.041,16.098 42.942,15.197 42.942,12.833 42.269,12.16 42.269,10.36 44.364,8.265 48.934,8.265 49.06,8.138 v1(50.895,8.138) ; 40.407,46.059 40.414,46.066 40.414,48.401 v1@42.45,50.437
  Bottom Layer w0.2: v1(50.895,8.138) 51.617,8.138 51.829,8.35 51.647,8.168 CN12.18@51.86,7.955
  other v1: 42.45,50.463
PB8: CN12.20 R24.1 R28.1 R35.1 R99.2 R109.2 U5.70 U29.4 | length 106.7
  Top Layer w0.2: v1(23.421,33.996) v1(36.944,33.996) v1@37.03,34.082 ; v1@39.493,40.294 U5.70@40.613,40.294 ; v1@50.184,9.493 50.285,9.493 v1@50.371,9.407 ; v1(50.285,9.407) v1@50.371,9.407 ; R28.1@59.329,21.659 59.329,20.385 58.053,19.108 58.053,17.715 60.132,15.636 60.132,10.375 58.836,9.079 56.484,9.079 56.156,9.407 v1@50.371,9.407 ; R28.1@59.355,21.48 60.504,20.331 68.497,20.331 R35.1@68.792,20.626
  POWER w0.2: v1@36.865,34.082 36.865,37.302 37.317,37.754 39.516,39.953 v1(39.516,40.176) ; v1@37.03,34.082 36.945,33.997 36.945,32.798 36.645,32.498 36.645,29.968 36.238,29.561 36.238,28.784 35.9,28.446 35.9,24.071 35.433,23.603 35.433,23.153 34.659,22.379 34.659,21.47 34.662,21.467 34.662,19.272 33.572,18.182 33.572,9.122 34.961,7.732 42.634,7.732 43.701,6.665 48.059,6.665 v1(48.304,6.42)
  Bottom Layer w0.2: U29.4@20.121,34.748 21.1,34.748 22.033,33.815 R109.2@22.308,33.815 ; R109.2@22.473,33.996 v1(23.421,33.996) 23.85,33.996 R99.2@24.093,34.239 ; v1(48.304,6.42) 48.812,6.42 49.32,6.928 CN12.20@49.32,7.955 49.599,8.234 49.599,9.595 49.787,9.407 v1(50.285,9.407)
PB8_C: P1.7 R120.2 U29.17 | length 8
  Bottom Layer w0.2: P1.7@8.15,32.246 P1.7@8.15,32.472 ; P1.7@8.15,32.776 8.479,32.776 10.263,34.561 11.362,34.561 12.107,33.815 13.04,34.748 U29.17@14.521,34.748
PB9: CN12.22 R23.1 R25.1 R38.1 R100.2 R108.2 U5.69 U29.5 | length 121.8
  Top Layer w0.2: v1(23.37,33.026) 25.891,33.026 26.254,32.663 33.206,32.663 33.569,33.026 v1(36.395,33.026) ; v1(38.609,40.197) 39.305,40.894 U5.69@40.613,40.894 ; v1(47.745,8.943) 47.831,8.857 56.14,8.857 56.318,8.679 59.001,8.679 60.532,10.21 60.532,16.568 58.778,18.321 R23.1@58.778,18.408 ; R23.1@58.91,18.408 R23.1@58.778,18.408 ; R25.1@59.269,25.834 60.034,25.069 60.034,21.944 61.192,20.787 67.617,20.787 68.332,21.502 69.27,21.502 69.478,21.294 69.478,19.486 R38.1@68.84,18.848 67.822,19.866 60.236,19.866 R23.1@58.778,18.408
  POWER w0.2: v1(36.395,33.026) v1@36.37,33.026 ; v1(38.609,40.197) 38.609,39.612 37.151,38.154 36.465,37.468 36.465,34.817 36.37,34.722 v1@36.37,33.026 ; v1(45.789,6.115) 45.789,6.143 45.706,6.226 43.575,6.226 42.468,7.332 34.796,7.332 33.172,8.956 33.172,18.348 34.262,19.438 34.262,21.302 34.259,21.304 34.259,22.545 35.033,23.319 35.033,23.769 35.5,24.236 35.5,28.612 35.838,28.95 35.838,29.727 36.245,30.134 36.245,32.901 v1@36.37,33.026
  Bottom Layer w0.2: U29.5@20.121,34.098 20.937,34.098 22.052,32.983 23.791,32.983 R100.2@23.906,32.867 ; v1(45.789,6.115) 46.122,6.115 46.805,6.798 46.805,7.93 CN12.22@46.78,7.955 CN12.22@47.32,8.495 ; CN12.22@47.332,8.943 v1(47.745,8.943)
PB9_C: P1.10 R121.2 U29.16 | length 16.1
  Bottom Layer w0.2: P1.10@8.15,38.246 8.547,38.246 8.862,38.56 14.113,38.56 15.767,36.906 15.767,34.391 15.474,34.098 U29.16@14.521,34.098 13.086,34.098 12.727,33.739 12.727,32.861 12.107,32.241 R121.2@12.107,32.122
PB10: CN12.24 TP15.1 U5.96 U8.6 | length 50.8
  Top Layer w0.2: v1(43.415,10.08) 42.433,11.062 42.433,11.815 42.583,11.965 42.583,13.896 42.223,14.256 42.223,23.851 44.685,26.313 45.35,26.313 47.585,28.548 48.053,28.548 50.635,31.129 v1(51.106,31.129) 51.106,34.786 U5.96@51.113,34.794 ; U5.96@51.017,34.889 U5.96@51.113,34.985 ; v1(55.234,28.287) 55.147,28.287 55.541,27.893 58.227,27.893 58.899,27.221 59.94,27.221 60.35,27.631 60.35,28.126 61.288,29.064 62.905,29.064 63.651,29.809 U8.6@63.651,30.039
  POWER w0.2: v1(51.106,31.129) 51.11,31.129 51.865,30.375 51.867,30.375 52.007,30.236 54.264,30.236 55.234,29.265 v1(55.234,28.287)
  Bottom Layer w0.2: v1(43.415,10.08) 44.24,9.255 CN12.24@44.24,7.955 ; CN12.24@44.765,8.992 44.765,7.236 44.779,7.222 CN12.24@44.77,7.214
PB11: CN12.26 SB28.2 SB43.1 U5.97 | length 62.2
  Top Layer w0.2: v1(42.983,11.462) 42.983,14.062 42.623,14.421 42.623,23.685 44.851,25.913 45.516,25.913 47.751,28.148 48.219,28.148 50.286,30.215 v1(51.106,30.215) 51.656,30.765 51.656,31.357 51.506,31.507 51.506,33.026 51.713,33.233 U5.97@51.713,34.794 ; v1(53.71,29.668) 53.727,29.652 54.107,29.652 54.368,29.913 56.176,29.913 56.345,30.082 57.004,30.082 57.91,30.987 58.451,30.987 59.855,32.391 59.855,38.144 61.386,39.676 66.655,39.676 67.809,38.522 67.809,37.246 68.082,36.973
  POWER w0.2: v1(51.106,30.215) 51.485,29.836 53.543,29.836 v1(53.71,29.668)
  Bottom Layer w0.2: CN12.26@41.7,7.955 41.7,9.274 42.983,10.556 v1(42.983,11.462) ; CN12.26@42.149,9.119 42.149,7.294 CN12.26@42.23,7.214 ; 50.032,30.215 v1(51.106,30.215)
PB14: CN12.28 R90.2 SB49.1 U5.92 | length 69.7
  Top Layer w0.2: v1(41.265,10.872) 41.865,11.472 41.865,12.374 40.6,13.64 40.6,15.131 41.023,15.554 41.023,24.348 44.188,27.513 44.853,27.513 47.088,29.748 47.556,29.748 48.831,31.023 48.831,33.362 48.713,33.48 U5.92@48.713,34.794 48.713,35.735 47.72,36.728 43.722,36.728 v1(42.477,37.972)
  POWER w0.2: v1(26.316,31.146) 29.83,31.146 31.045,32.361 31.045,37.859 v1(31.115,37.929)
  Bottom Layer w0.2: 25.669,31.146 v1(26.316,31.146) ; R90.2@30.171,41.914 31.527,40.558 31.527,38.255 31.52,38.248 ; v1(31.115,37.929) 31.201,37.929 31.52,38.248 ; CN12.28@39.16,7.955 39.16,9.829 39.882,10.551 40.944,10.551 v1(41.265,10.872) ; CN12.28@39.323,8.936 39.323,9.957 ; v1(42.477,37.972) 42.08,37.972 41.805,38.248 36.883,38.248 36.874,38.239 31.529,38.239 31.52,38.248
PB14_C: P1.20 U29.15 | length 16.2
  Bottom Layer w0.2: P1.20@6.15,38.246 7.2,39.296 8.806,39.296 9.142,38.96 14.357,38.96 16.167,37.15 16.167,34.208 15.407,33.448 U29.15@14.521,33.448
PB15: CN12.32 R101.2 U5.91 | length 67.5
  Top Layer w0.2: v1(41.315,11.786) 41.315,12.359 40.2,13.474 40.2,15.296 40.623,15.719 40.623,24.513 44.023,27.913 44.687,27.913 46.923,30.148 47.39,30.148 48.431,31.188 48.431,33.196 48.113,33.514 U5.91@48.113,34.794 48.113,35.557 47.342,36.328 43.344,36.328 41.927,37.745 41.927,38.718 v1(42.02,38.811)
  Bottom Layer w0.2: R101.2@25.32,41.978 25.32,42.047 26.039,42.766 31.308,42.766 32.112,41.962 32.112,39.149 32.622,38.639 36.708,38.639 36.717,38.648 41.857,38.648 v1(42.02,38.811) ; CN12.32@34.08,7.955 34.08,10.538 35.042,11.501 38.709,11.501 38.969,11.761 41.315,11.761 v1(41.315,11.786)
PC0: CN12.37 SB53.1 SB59.1 U5.58 | length 71.9
  Top Layer w0.2: v1(38.08,47.897) 38.822,47.897 39.164,47.554 40.552,47.554 U5.58@40.613,47.494 U5.58@40.613,47.54
  POWER w0.2: v1@27.634,10.287 v1@27.691,10.345 ; v1(27.755,10.281) 29.616,12.141 29.616,16.407 28.912,17.111 28.912,17.905 v1@29.018,18.012 ; v1(28.926,18.105) 28.738,18.292 28.738,22.448 32.3,26.01 32.3,29.937 32.638,30.276 32.638,31.052 33.045,31.459 33.045,31.465 ; 33.045,31.51 33.045,35.922 33.265,36.143 33.265,38.793 33.792,39.32 33.792,40.642 34.349,41.199 34.349,42.893 37.476,46.019 37.476,47.292 v1(38.08,47.897)
  Bottom Layer w0.2: 12.15,20.504 12.885,21.238 14.939,21.238 15.427,20.75 ; 15.003,20.438 16.704,18.737 28.293,18.737 v1(28.926,18.105) ; CN12.37@26.46,3.005 26.46,4.122 27.755,5.417 v1(27.755,10.281) ; v1@27.634,10.281 v1@27.634,10.287
PC0_C: P1.13 SB57.2 SB59.2 | length 8.8
  Bottom Layer w0.2: P1.13@6.15,24.246 7.15,23.246 9.133,23.246 9.655,22.724 9.655,21.276 10.756,20.174 SB57.2@10.756,18.584 SB57.2@10.721,18.619
PC1: CN12.41 U5.60 U27.3 | length 68.6
  Top Layer w0.2: v1(39.861,46.296) 40.61,46.296 U5.60@40.613,46.294
  POWER w0.2: v1(20.161,5.124) 20.161,7.17 21.043,8.052 28.202,8.052 31.41,11.26 v1(31.41,15.842) 31.572,16.004 31.572,18.699 30.338,19.933 30.338,21.786 33.9,25.347 33.9,29.275 34.238,29.613 34.238,30.39 34.645,30.796 34.645,35.26 34.865,35.48 34.865,38.131 35.392,38.657 35.392,39.979 35.949,40.536 35.949,42.216 v1@39.851,46.117
  Bottom Layer w0.2: v1(20.161,5.124) CN12.41@21.38,3.905 ; U27.3@20.353,16.704 21.388,16.704 21.888,16.204 26.349,16.204 26.497,16.352 27.616,16.352 28.135,15.833 28.144,15.842 v1(31.41,15.842) ; 20.599,4.743 CN12.41@20.821,4.743
PC1_C: P1.11 U27.18 | length 12.7
  Bottom Layer w0.2: P1.11@6.15,20.246 6.15,16.618 6.622,16.145 12.906,16.145 13.464,16.704 U27.18@14.753,16.704
PC2: CN12.43 SB14.1 SB15.1 U5.59 | length 90.4
  Top Layer w0.2: v1@39.398,46.894 U5.59@40.613,46.894 ; 55.292,19.837 55.51,20.055 56.753,20.055 ; SB14.1@55.355,20.291 55.382,20.318 ; 56.769,20.072 56.753,20.055 ; v1(57.559,20.055) 56.753,20.055
  POWER w0.2: v1(18.84,5.138) 18.84,7.881 19.569,8.611 28.182,8.611 30.86,11.289 30.86,17.544 v1(31.013,17.697) 31.013,18.675 29.938,19.75 29.938,21.951 33.5,25.513 33.5,29.44 33.838,29.778 33.838,30.555 34.245,30.962 34.245,35.425 34.465,35.646 34.465,38.296 34.992,38.823 34.992,40.145 35.549,40.702 35.549,42.395 39.301,46.147 39.295,46.154 v1(39.295,47.004)
  Bottom Layer w0.2: CN12.43@18.84,3.005 v1(18.84,5.138) ; v1(31.013,17.697) 31.351,18.036 34.837,18.036 35.473,18.672 45.1,18.672 45.547,19.119 47.385,19.119 47.602,18.902 48.585,18.902 49.237,19.554 49.237,20.238 49.401,20.402 53.424,20.402 53.754,20.072 57.543,20.072 v1(57.559,20.055)
PC3: CN12.45 SB10.1 U5.61 | length 90.3
  Top Layer w0.2: v1(38.685,46.319) 39.31,45.694 U5.61@40.613,45.694 ; v1(48.279,23.027) 48.279,25.058 49.465,26.244 SB10.1@52.074,26.244
  POWER w0.2: v1(16.344,5.182) 16.344,7.468 17.893,9.017 27.835,9.017 30.46,11.642 v1(30.461,18.435) ; v1@30.317,18.442 30.317,18.594 29.538,19.372 29.538,22.117 33.1,25.679 33.1,29.606 33.438,29.944 33.438,30.721 33.845,31.128 33.845,35.591 34.065,35.811 34.065,38.462 34.592,38.989 34.592,40.31 35.149,40.868 35.149,42.561 38.685,46.097 v1(38.685,46.319)
  Bottom Layer w0.2: CN12.45@16.3,3.005 16.344,3.049 v1(16.344,5.182) ; v1@30.439,18.436 34.671,18.436 35.307,19.072 44.91,19.072 45.363,19.525 47.545,19.525 47.768,19.302 48.407,19.302 48.837,19.732 48.837,20.19 48.376,20.651 48.376,22.93 v1(48.279,23.027) ; v1@30.44,18.435 v1(30.461,18.435)
PC6: CN12.34 R113.2 U5.94 | length 75.5
  Top Layer w0.2: v1(41.992,13.586) 41.823,13.755 41.823,24.016 44.52,26.713 45.184,26.713 47.42,28.948 47.888,28.948 49.824,30.885 49.824,34.705 U5.94@49.913,34.794 49.913,35.451 ; v1(42.936,38.836) 43.027,38.744 43.027,38.004 43.903,37.128 48.236,37.128 49.913,35.451 ; U5.94@49.913,35.243 49.913,35.451
  Bottom Layer w0.2: R113.2@20.53,41.978 20.53,42.103 21.206,42.778 25.459,42.778 25.846,43.166 31.51,43.166 32.512,42.164 32.512,39.573 32.798,39.288 35.315,39.288 35.784,39.757 36.783,39.757 37.492,39.048 41.479,39.048 41.792,39.361 42.411,39.361 v1(42.936,38.836) ; CN12.34@31.54,7.955 31.54,9.403 35.177,13.04 38.478,13.04 38.822,13.383 41.79,13.383 v1(41.992,13.586)
PC7: CN12.36 SB37.1 U5.10 | length 59.1
  Top Layer w0.2: v1(43.554,14.119) 43.023,14.65 43.023,23.519 45.017,25.513 45.681,25.513 47.917,27.748 48.385,27.748 50.267,29.63 51.555,29.63 51.83,29.904 52.555,29.904 53.126,30.476 53.126,31.038 53.444,31.356 54.045,31.356 54.289,31.113 55.679,31.113 56.061,31.494 56.061,32.248 57.129,33.316 57.129,33.567 57.391,33.829 57.391,36.318 v1(57.285,36.423) ; v1(53.758,41.488) 54.353,40.894 U5.10@55.013,40.894
  Bottom Layer w0.2: CN12.36@29,7.955 29,9.372 33.768,14.14 35.193,14.14 35.55,13.783 41.269,13.783 41.633,14.147 43.526,14.147 v1(43.554,14.119) ; v1(53.758,41.488) 54.397,41.488 54.397,41.719 ; 54.795,41.718 54.795,41.512 55.479,40.829 55.479,40.41 57.319,38.569 57.319,36.354 57.285,36.388 v1(57.285,36.423)
PC9: CN12.38 U5.93 U27.4 | length 54.7
  Top Layer w0.2: v1(41.231,14.589) 41.423,14.782 41.423,24.182 44.354,27.113 45.019,27.113 47.254,29.348 47.722,29.348 49.317,30.943 U5.93@49.317,34.787 ; U5.93@49.313,34.794 49.317,34.79 U5.93@49.317,34.787 ; U5.93@49.323,34.794 U5.93@49.317,34.787
  Bottom Layer w0.2: 21.215,16.054 U27.4@20.353,16.054 21.416,16.054 21.666,15.804 26.641,15.804 26.789,15.952 27.315,15.952 27.748,15.519 27.748,14.54 ; CN12.38@26.46,7.955 26.46,11.214 27.748,12.502 27.748,14.54 ; v1(41.231,14.589) 40.86,14.218 35.68,14.218 35.359,14.54 27.748,14.54
PC9_C: P1.14 U27.17 | length 20.3
  Top Layer w0.2: v1(4.93,17.974) 4.93,25.026 P1.14@6.15,26.246
  Bottom Layer w0.2: v1(4.93,17.974) 4.93,16.882 6.067,15.745 13.071,15.745 13.38,16.054 U27.17@14.753,16.054
PC10: CN12.40 U1.14 U5.80 U27.5 | length 50.4
  Top Layer w0.2: U1.14@27.05,24.999 27.066,25.015 v1(27.066,27.428) 27.33,27.692 27.33,28.908 27.828,29.406 31.611,29.406 32.809,30.604 39.883,30.604 40.621,31.342 40.621,32.036 41.513,32.928 U5.80@41.513,34.794
  POWER w0.2: v1(27.024,15.392) 26.338,16.078 26.338,24.721 27.066,25.449 v1(27.066,27.428)
  Bottom Layer w0.2: U27.5@20.353,15.404 v1@27.024,15.404 ; CN12.40@23.92,7.955 23.92,9.239 26.06,11.379 26.06,11.38 27.348,12.668 27.348,15.069 v1(27.024,15.392)
PC10_C: SB54.1 U27.16 | length 3.1
  Bottom Layer w0.2: SB54.1@11.925,14.901 12.984,14.901 13.429,15.345 14.753,15.345 U27.16@14.753,15.404
PC11: CN12.42 U1.13 U5.77 U27.6 | length 52.5
  Top Layer w0.2: U1.13@26.35,24.999 v1(26.35,26.78) 26.35,27.626 26.918,28.194 26.918,29.898 28.239,31.219 38.85,31.219 v1(38.902,31.167) ; v1(39.36,33.754) 39.36,34.363 39.463,34.466 39.463,35.591 39.965,36.094 U5.77@40.613,36.094
  POWER w0.2: v1(26.331,14.792) 26.331,15.326 25.938,15.719 25.938,24.887 26.35,25.299 v1(26.35,26.78) ; v1(38.902,31.167) 38.945,31.209 38.945,32.378 39.36,32.793 v1(39.36,33.754)
  Bottom Layer w0.2: U27.6@20.353,14.754 20.403,14.804 20.415,14.792 v1(26.331,14.792) 26.948,14.176 26.948,12.834 25.66,11.546 25.66,11.544 24.334,10.218 22.491,10.218 21.38,9.107 CN12.42@21.38,7.955
PC11_C: SB55.1 U27.15 | length 3.4
  Bottom Layer w0.2: SB55.1@11.898,13.402 12.051,13.402 13.402,14.754 U27.15@14.753,14.754
PC12: CN12.44 U1.15 U5.78 U27.7 | length 54.5
  Top Layer w0.2: U1.15@27.75,24.999 27.73,25.019 v1(27.73,26.816) 27.73,28.638 28.099,29.006 31.777,29.006 32.972,30.201 38.755,30.201 v1(38.902,30.054) ; v1(39.93,32.775) 39.91,32.795 39.91,33.263 39.91,34.172 39.863,34.219 39.863,35.339 40.017,35.494 U5.78@40.613,35.494
  POWER w0.2: v1(26.338,13.868) 27.275,13.868 27.616,14.209 27.616,15.578 26.738,16.456 26.738,24.353 27.73,25.344 v1(27.73,26.816) ; v1(38.902,30.054) 38.902,30.389 39.452,30.939 39.452,32.297 v1(39.93,32.775)
  Bottom Layer w0.2: CN12.44@18.84,7.955 18.84,9.138 20.32,10.618 24.168,10.618 25.26,11.71 25.26,11.711 26.338,12.79 v1(26.338,13.868) 25.837,14.37 21.825,14.37 21.558,14.104 U27.7@20.353,14.104
PC12_C: SB56.1 U27.14 | length 3.5
  Bottom Layer w0.2: 12.498,12.219 12.898,12.619 12.898,13.445 13.556,14.104 U27.14@14.753,14.104
PC13: CN12.46 SB2.1 U5.62 | length 62.2
  Top Layer w0.2: 36.343,49.62 36.573,49.62 ; 36.531,49.202 36.531,49.142 36.654,49.142 37.355,48.441 37.355,47.844 38.05,47.149 v1@38.05,46.997 ; v1(38.047,46.997) 38.047,46.153 39.107,45.094 U5.62@40.613,45.094
  POWER w0.2: v1@17.287,9.449 27.701,9.449 30.016,11.764 30.016,16.572 29.476,17.113 29.476,18.332 29.138,18.67 29.138,22.283 32.7,25.844 32.7,29.772 33.038,30.11 33.038,30.887 33.445,31.293 33.445,35.757 33.665,35.977 33.665,38.628 34.192,39.154 34.192,40.476 34.749,41.033 34.749,42.727 38.026,46.003 38.021,46.008 38.05,46.037 38.025,46.062 38.05,46.088 v1@38.05,46.954
  Bottom Layer w0.2: CN12.46@16.3,7.955 16.572,8.227 16.572,9.322 16.725,9.474 v1(17.287,9.474)
PH0: CN12.47 SB26.2 U5.55 U27.8 | length 107.7
  Top Layer w0.2: v1(18.71,10.281) 18.71,12.948 v1(19.192,13.43) ; v1(39.718,49.091) 39.92,49.294 U5.55@40.613,49.294 ; 71.714,49.823 71.825,49.933 v1(72.216,49.933)
  POWER w0.2: v1(13.86,5.156) 13.86,7.281 16.859,10.281 v1(18.71,10.281) 18.934,10.056 26.731,10.056 29.216,12.541 29.216,16.241 28.338,17.119 28.338,22.614 31.9,26.176 31.9,30.103 32.238,30.441 32.238,31.218 32.645,31.625 32.645,36.088 32.865,36.308 32.865,38.959 33.392,39.486 33.392,40.807 33.949,41.365 33.949,43.058 37.076,46.185 37.076,48.041 38.126,49.091 v1(39.718,49.091) ; v1(57.354,46.039) 58.352,47.037 69.32,47.037 v1(72.216,49.933)
  Bottom Layer w0.2: CN12.47@13.76,4.298 CN12.47@13.76,3.005 13.86,3.105 v1(13.86,5.156) ; v1@19.192,13.401 v1(19.192,13.43) 20.279,13.43 20.304,13.405 U27.8@20.353,13.454 ; v1@39.703,48.961 v1@39.718,48.961 ; v1(39.718,49.091) 40.096,48.713 45.564,48.713 45.958,48.319 46.593,48.319 46.809,48.103 50.44,48.103 50.774,48.437 54.014,48.437 55.895,46.556 56.837,46.556 v1(57.354,46.039)
PH0_C: P1.12 U27.13 | length 24.6
  Bottom Layer w0.2: P1.12@6.15,22.246 4.409,22.246 2.82,20.656 2.82,15.463 5.807,12.476 8.847,12.476 10.1,11.223 12.843,11.223 13.298,11.678 13.298,13.072 13.68,13.454 U27.13@14.753,13.454
PH1: CN12.49 R96.2 U5.54 | length 74
  Top Layer w0.2: v1(39.211,49.894) U5.54@40.613,49.894 U5.54@40.713,49.794
  POWER w0.2: v1(11,5.25) 11,6.345 11.787,7.133 12.615,7.133 16.313,10.831 18.938,10.831 19.312,10.456 26.565,10.456 28.816,12.707 28.816,16.075 27.938,16.953 27.938,22.78 31.5,26.341 31.5,30.481 v1(31.688,30.669) 31.688,31.234 32.245,31.79 32.245,36.254 32.465,36.474 32.465,39.125 32.992,39.652 32.992,40.973 33.549,41.531 33.549,43.224 36.676,46.35 36.676,48.207 38.363,49.894 v1(39.211,49.894)
  Bottom Layer w0.2: v1(11,5.25) 11,3.225 CN12.49@11.22,3.005 ; R96.2@26.918,29.605 26.918,30.184 27.379,30.645 31.664,30.645 v1(31.688,30.669)
PH3: CN12.50 R11.2 U5.63 | length 65.3
  Top Layer w0.2: v1(35.722,47.338) 35.781,47.338 36.304,47.86 36.304,48.172 37.449,47.027 37.449,46.149 39.104,44.494 U5.63@40.613,44.494
  POWER w0.2: v1(12.182,7.965) 15.46,11.243 19.116,11.243 19.503,10.856 26.4,10.856 28.416,12.873 28.416,15.91 27.538,16.787 27.538,22.946 31.1,26.507 31.1,31.285 31.845,32.03 31.845,36.419 32.065,36.64 32.065,39.29 32.592,39.817 32.592,41.139 33.149,41.696 33.149,43.39 35.722,45.963 v1(35.722,47.338) ; v1@35.816,47.342 v1@35.816,47.393
  Bottom Layer w0.2: CN12.50@11.22,7.955 11.21,7.965 v1(12.182,7.965)
PMU_AT_IN: CN13.47 R78.1 SB45.1 U5.37 | length 53.4
  Top Layer w0.2: U5.37@49.313,51.794 49.313,53.842 v1(49.35,53.879)
  POWER w0.2: v1(17.42,65.645) 18.98,64.085 25.154,64.085 27.154,66.086 43.228,66.086 46.101,63.212 46.101,59.987 v1@46.774,59.315
  Bottom Layer w0.2: CN13.47@13.76,69.045 13.76,67.934 14.921,66.773 16.292,66.773 v1(17.42,65.645) ; v1@46.662,59.382 v1@46.665,59.382 ; v1(46.665,59.41) 47.533,59.41 47.834,59.109 47.834,58.574 ; 47.725,58.016 47.172,57.462 47.172,54.42 47.396,54.195 49.034,54.195 v1(49.35,53.879) ; 47.965,58.443 47.834,58.574 ; R78.1@49.475,58.94 49.109,58.574 47.834,58.574
PMU_AT_OUT: CN13.49 SB45.2 U5.35 | length 55.2
  Top Layer w0.254: U5.35@50.513,51.794 50.513,53.645 v1(50.518,53.651)
  POWER w0.254: v1(12.058,66.99) 13.305,66.99 17.837,62.458 25.828,62.458 27.718,64.349 42.664,64.349 44.474,62.538 44.474,58.607 45.193,57.889 v1(45.193,57.807)
  Bottom Layer w0.254: CN13.49@11.22,69.045 11.22,67.777 12.058,66.938 v1(12.058,66.99) ; v1(45.193,57.807) 45.777,57.807 46.133,58.164 46.604,58.164 46.604,54.188 47.023,53.768 48.438,53.768 48.904,53.302 50.17,53.302 v1(50.518,53.651)
PMU_VBACKUP: CN13.4 U5.36 | length 36.8
  Top Layer w0.2: U5.36@49.913,51.794 49.913,54.412 50.345,54.845 51.621,54.845 52.179,55.403 52.179,58.379 52.975,59.175 53.923,59.175 54.968,60.219 v1(54.968,62.187)
  Bottom Layer w0.2: v1@54.914,62.187 v1(54.968,62.187) 55.288,62.507 58.497,62.507 59.115,63.125 61.293,63.125 62.96,64.792 66.161,64.792 68.357,66.988 68.357,71.507 69.64,72.79 CN13.4@69.64,73.995
PWR_ENn: R63.1 U12.28 U16.4 | length 31.1
  Top Layer w0.2: U12.28@78.519,49.338 79.209,49.338 79.791,49.92 81.973,49.92 82.584,50.531 83.173,50.531 83.448,50.806 v1(84.172,50.806) ; v1(92.515,69.992) 92.515,69.15 R63.1@92.517,69.149 ; R63.1@92.54,69.126 U16.4@93.787,69.126
  Bottom Layer w0.2: v1(84.172,50.806) 84.172,53.342 85.105,54.275 85.105,56.603 90.769,62.267 90.769,68.246 v1(92.515,69.992) 92.515,69.965 v1@92.541,69.939
QSPI_NCS: R40.2 SB28.1 TP20.1 U8.1 | length 5.4
  Top Layer w0.2: U8.1@66.191,37.037 68.212,35.016 ; R40.2@68.212,34.153 68.212,35.016 ; 68.212,35.208 68.212,35.016 ; R40.2@68.233,34.132 TP20.1@69.757,34.132
RECOVERY: Q1.3 R53.1 U17.C1 | length 5.2
  Top Layer w0.2: R53.1@88.667,14.01 88.853,14.196 91.141,14.196 91.941,14.996 91.941,15.793 92.298,16.15 U17.C1@92.499,16.15
RECOVERYn: B5.2 B5.4 Q1.1 R65.2 U17.B2 | length 20.7
  Top Layer w0.2: Q1.1@90.471,12.422 91.161,13.112 93.249,13.112 93.727,13.59 93.727,16.235 93.312,16.65 U17.B2@92.999,16.65 ; R65.2@93.68,13.31 94.715,13.31 95.68,12.345 B5.2@95.68,6.475 B5.4@95.68,1.325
